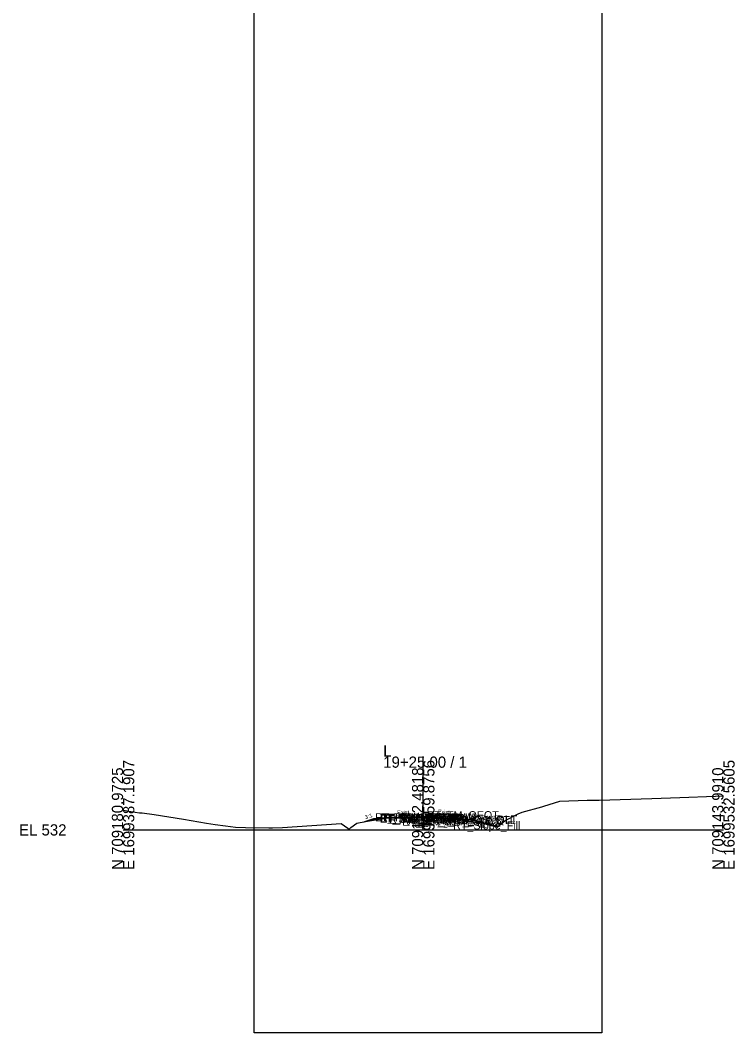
# Model space of a CAD drawing. Extents: x -63 to 1153, y -24 to 9522.
# Drawn here: x 974.3 to 1152.8, y 1449.3 to 1702.4 of the extents above; entities that cross this region are included whole.
import ezdxf

# ---------------------------------------------------------------- set-up
doc = ezdxf.new("R2010")
doc.units = 0
for name, color, linetype in [('Default', 7, 'Continuous'), ('Exist Cross Section Cell', 7, 'Continuous'), ('Exist XS Center Line Elevation Label', 7, 'Continuous'), ('Exist XS Ground Line', 7, 'Continuous'), ('Prop CMT DNC', 7, 'Continuous'), ('Prop CMT Pvmt Surface Overlay', 7, 'Continuous'), ('Prop CMT Slope Grass', 7, 'Continuous'), ('Prop XS Earthwork Shape', 7, 'Continuous'), ('Prop XS EOT Tick Mark', 7, 'Continuous'), ('Prop XS SE Text', 7, 'Continuous'), ('Prop XS Side Slope Text', 7, 'Continuous')]:
    doc.layers.add(name, color=color, linetype=linetype)

msp = doc.modelspace()

# ---------------------------------------------------------------- linework, layer by layer
at = {"layer": 'Exist Cross Section Cell'}
for p, q in [((1075, 1500), (1075, 1518.34)), ((1000, 1500), (1075, 1500)), ((1075, 1500), (1150, 1500))]:
    msp.add_line(p, q, dxfattribs=at)
at = {"layer": 'Exist XS Ground Line'}
msp.add_lwpolyline([(1000, 1504.94), (1001.97, 1504.63), (1004.07, 1504.3), (1004.73, 1504.25), (1007.79, 1503.83), (1015.07, 1502.65), (1020.84, 1501.72), (1023.04, 1501.35), (1025.6, 1501.02), (1028.05, 1500.72), (1030.56, 1500.58), (1036.4, 1500.48), (1037.34, 1500.48), (1039.82, 1500.62), (1054.48, 1501.59), (1056.19, 1500.44), (1056.51, 1500.22), (1056.66, 1500.33), (1056.91, 1500.56), (1058.39, 1501.68), (1060.59, 1502.09), (1065.55, 1502.96), (1072.07, 1503.04), (1075, 1503.07), (1075.27, 1503.07), (1082.03, 1502.64), (1084.79, 1502.43), (1086.71, 1502.08), (1087.46, 1501.98), (1089.47, 1501.73), (1092.42, 1501.01), (1093.44, 1500.69), (1093.96, 1501.09), (1095.5, 1502.39), (1098.69, 1503.98), (1099.73, 1504.46), (1104.67, 1505.8), (1104.86, 1505.87), (1105.15, 1505.92), (1109.15, 1507.2), (1115.99, 1507.41), (1116.92, 1507.41), (1117.29, 1507.4), (1118.96, 1507.44), (1132.14, 1507.85), (1139.15, 1508.06), (1148.04, 1508.45), (1150, 1508.51)], dxfattribs=at)
at = {"layer": 'Prop CMT DNC'}
msp.add_lwpolyline([(1032.78, 2560.22), (1119.63, 2560.22), (1119.63, 1449.3), (1032.78, 1449.3)], close=True, dxfattribs=at)
at = {"layer": 'Prop CMT Pvmt Surface Overlay'}
msp.add_line((1075, 1503.28), (1065.55, 1503.03), dxfattribs=at)
msp.add_lwpolyline([(1075, 1503.28), (1085, 1502.68)], dxfattribs=at)
at = {"layer": 'Prop CMT Slope Grass'}
for p, q in [((1065.55, 1503.03), (1065.55, 1502.96)), ((1085, 1502.68), (1085, 1502.4))]:
    msp.add_line(p, q, dxfattribs=at)
for points in [[(1062.56, 1502.79), (1060.32, 1502.04)], [(1065.55, 1503.03), (1062.56, 1502.79)], [(1085, 1502.68), (1088, 1502.44)], [(1088, 1502.44), (1091.99, 1501.11)]]:
    msp.add_lwpolyline(points, dxfattribs=at)
at = {"layer": 'Prop XS Earthwork Shape'}
for points in [[(1065.55, 1503.03), (1065.55, 1502.96), (1060.59, 1502.09), (1060.32, 1502.04), (1062.56, 1502.79)], [(1089.47, 1501.73), (1091.99, 1501.11), (1088, 1502.44), (1085, 1502.68), (1085, 1502.4), (1086.71, 1502.08), (1087.46, 1501.98)]]:
    msp.add_lwpolyline(points, close=True, dxfattribs=at)
at = {"layer": 'Prop XS EOT Tick Mark'}
msp.add_lwpolyline([(1065.55, 1503.03), (1065.55, 1504.03)], dxfattribs=at)

# ---------------------------------------------------------------- texts
at = {"layer": 'Default'}
msp.add_text('-', height=0.0001, dxfattribs=at).set_placement((1000, 1500))
msp.add_text('-', height=0.0001, dxfattribs=at).set_placement((1000, 1500))
at = {"layer": 'Exist Cross Section Cell'}
for s, p in [('L', (1065, 1518.34)), ('19+25.00 / 1', (1065, 1515.54)), ('EL 532', (974, 1498.6))]:
    msp.add_text(s, height=2.8, dxfattribs=at).set_placement(p)
for s, p in [('E 1699387.1907', (1002.8, 1490)), ('E 1699459.8756', (1077.8, 1490)), ('E 1699532.5605', (1152.8, 1490)), ('N 709180.9725', (1000, 1490)), ('N 709162.4818', (1075, 1490)), ('N 709143.9910', (1150, 1490))]:
    msp.add_text(s, height=2.8, rotation=90, dxfattribs=at).set_placement(p)
at = {"layer": 'Exist XS Center Line Elevation Label'}
msp.add_text('535.07', height=1, dxfattribs=at).set_placement((1072.85, 1500.74))
at = {"layer": 'Prop CMT DNC'}
for s, p in [('RT_PV1_OEEOP_W', (1062.94, 1502.16)), ('LT_PV1_OEEOP_W', (1062.98, 1502.16)), ('RT_Sub_OEEOP', (1064.17, 1501.78)), ('LT_Sub_OEEOP', (1064.21, 1501.78)), ('RT_PV2_OEEOP', (1064.26, 1502.03)), ('LT_PV2_OEEOP', (1064.31, 1502.03)), ('RT_Sub_Trench_Out_DLT', (1066.51, 1501.6)), ('PV1_PGL_W', (1067.58, 1502.16)), ('PV1_PGL', (1069.47, 1502.28)), ('RT_Sub_Trench_Out', (1069.7, 1501.15)), ('RT_PS2_Shelf_Out', (1071.21, 1501.42)), ('RT_Sub_OEOT', (1075.03, 1501.18)), ('RT_PV2_OEOT', (1075.13, 1501.43)), ('RT_PS2_OEOP', (1075.46, 1501.42)), ('RT_PV1_OEOT', (1075.69, 1501.68)), ('RT_PS1_OEOP', (1075.77, 1501.68)), ('RT_TM_OEOT', (1075.9, 1502.68)), ('RT_GS_OS_CTL', (1077.32, 1501.44)), ('RT_Slope_Fill', (1082.46, 1500.11))]:
    msp.add_text(s, height=2, dxfattribs=at).set_placement(p)
at = {"layer": 'Prop XS SE Text'}
for rotation, p in [(2.0996, (1068.51, 1503.87)), (356.5634, (1078.6, 1504.07))]:
    msp.add_text('Exist.', height=1, rotation=rotation, dxfattribs=at).set_placement(p)
at = {"layer": 'Prop XS Side Slope Text'}
for rotation, p in [(18.4332, (1060.59, 1502.65)), (341.5626, (1089.48, 1502.74)), (341.5625, (1089.48, 1502.74))]:
    msp.add_text('3:1', height=1, rotation=rotation, dxfattribs=at).set_placement(p)

doc.saveas('drawing.dxf')
